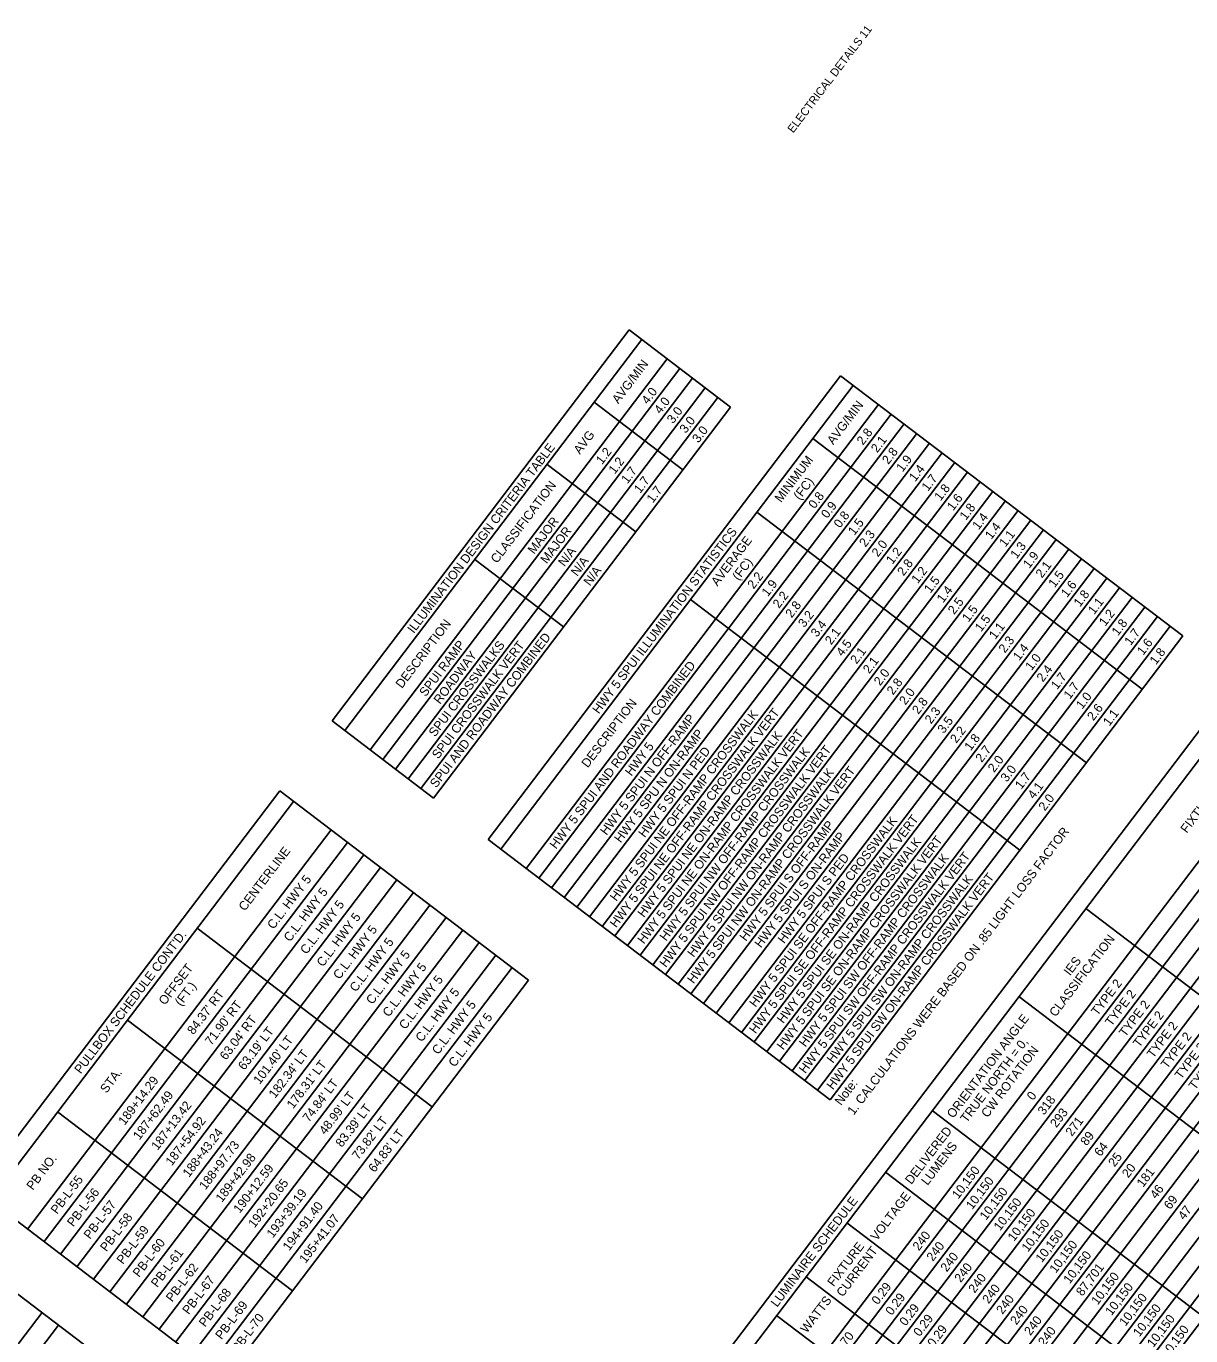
# Model space of a CAD drawing. Extents: x 1289840 to 1300285, y 220865 to 232462.
# Drawn here: x 1298836 to 1299692, y 231499 to 232462 of the extents above; entities that cross this region are included whole.
import ezdxf

# ---------------------------------------------------------------- set-up
doc = ezdxf.new("R2010")
doc.units = 0
for name, color, linetype in [('Default', 7, 'Continuous'), ('R_Border', 7, 'Continuous'), ('R_No Plot', 7, 'Continuous')]:
    doc.layers.add(name, color=color, linetype=linetype)

msp = doc.modelspace()

# ---------------------------------------------------------------- linework, layer by layer
at = {"layer": 'Default'}
for p, q in [((1299060.76, 231951.29), (1299279.23, 232238.61)), ((1299070.07, 231944.21), (1299288.55, 232231.52)), ((1299353.74, 232181.95), (1299279.23, 232238.61)), ((1299088.69, 231930.05), (1299307.17, 232217.36)), ((1299098.01, 231922.96), (1299316.49, 232210.28)), ((1299107.32, 231915.88), (1299325.8, 232203.2)), ((1299175.42, 231864.1), (1299434.62, 232204.96)), ((1299686.08, 232013.75), (1299434.62, 232204.96)), ((1299116.63, 231908.8), (1299335.11, 232196.11)), ((1299184.74, 231857.02), (1299443.93, 232197.88)), ((1299125.95, 231901.72), (1299344.42, 232189.03)), ((1299135.26, 231894.64), (1299353.74, 232181.95)), ((1299203.36, 231842.85), (1299462.56, 232183.72)), ((1299318.68, 232135.85), (1299253.49, 232185.42)), ((1299212.67, 231835.77), (1299471.87, 232176.63)), ((1298957.38, 230970.03), (1299864.22, 232162.59)), ((1299221.99, 231828.69), (1299481.19, 232169.55)), ((1299231.3, 231821.61), (1299490.5, 232162.47)), ((1298967.62, 230962.24), (1299874.46, 232154.8)), ((1299240.61, 231814.52), (1299499.81, 232155.39)), ((1299656.33, 231974.64), (1299414.19, 232158.77)), ((1299249.93, 231807.44), (1299509.13, 232148.31)), ((1299283.98, 232090.21), (1299218.79, 232139.79)), ((1299259.24, 231800.36), (1299518.44, 232141.23)), ((1299268.55, 231793.28), (1299527.75, 232134.14)), ((1299003.48, 230934.98), (1299910.32, 232127.54)), ((1299277.87, 231786.2), (1299537.07, 232127.06)), ((1299013.72, 230927.19), (1299920.56, 232119.75)), ((1299287.18, 231779.12), (1299546.38, 232119.98)), ((1299023.97, 230919.4), (1299930.81, 232111.96)), ((1299296.49, 231772.03), (1299555.69, 232112.9)), ((1299305.81, 231764.95), (1299565.01, 232105.82)), ((1299615.26, 231920.62), (1299373.11, 232104.75)), ((1299034.21, 230911.61), (1299941.05, 232104.17)), ((1299044.46, 230903.82), (1299951.3, 232096.38)), ((1299315.12, 231757.87), (1299574.32, 232098.73)), ((1299054.7, 230896.03), (1299961.54, 232088.59)), ((1299324.43, 231750.79), (1299583.63, 232091.65)), ((1299064.95, 230888.24), (1299971.79, 232080.8)), ((1299333.75, 231743.71), (1299592.95, 232084.57)), ((1299343.06, 231736.62), (1299602.26, 232077.49)), ((1299075.19, 230880.45), (1299982.03, 232073.01)), ((1299230.87, 232020.37), (1299165.67, 232069.94)), ((1299352.37, 231729.54), (1299611.57, 232070.41)), ((1299085.44, 230872.66), (1299992.28, 232065.22)), ((1299095.68, 230864.87), (1300002.52, 232057.43)), ((1299361.69, 231722.46), (1299620.88, 232063.32)), ((1299371, 231715.38), (1299630.2, 232056.24)), ((1299105.93, 230857.08), (1300012.76, 232049.64)), ((1299380.31, 231708.3), (1299639.51, 232049.16)), ((1299116.17, 230849.29), (1300023.01, 232041.85)), ((1299566.39, 231856.36), (1299324.25, 232040.49)), ((1299389.63, 231701.21), (1299648.82, 232042.08)), ((1299126.41, 230841.5), (1300033.25, 232034.06)), ((1299398.94, 231694.13), (1299658.14, 232035)), ((1299408.25, 231687.05), (1299667.45, 232027.91)), ((1299136.66, 230833.71), (1300043.5, 232026.27)), ((1299146.9, 230825.92), (1300053.74, 232018.48)), ((1299417.57, 231679.97), (1299676.76, 232020.83)), ((1299157.15, 230818.13), (1300063.99, 232010.69)), ((1299426.88, 231672.89), (1299686.08, 232013.75)), ((1299167.39, 230810.34), (1300074.23, 232002.9)), ((1299135.26, 231894.64), (1299060.76, 231951.29)), ((1298799.19, 231606.58), (1299022.27, 231899.95)), ((1299205.28, 231760.79), (1299022.27, 231899.95)), ((1298809.43, 231598.79), (1299032.52, 231892.16)), ((1298836.91, 231577.9), (1299059.99, 231871.27)), ((1299426.88, 231672.89), (1299175.42, 231864.1)), ((1298849.02, 231568.7), (1299072.1, 231862.06)), ((1298861.12, 231559.49), (1299084.2, 231852.86)), ((1298873.23, 231550.28), (1299096.31, 231843.65)), ((1298885.34, 231541.08), (1299108.42, 231834.44)), ((1298897.44, 231531.87), (1299120.53, 231825.24)), ((1298909.55, 231522.66), (1299132.63, 231816.03)), ((1298921.66, 231513.46), (1299144.74, 231806.82)), ((1299917.13, 231583.67), (1299614.91, 231813.47)), ((1298933.77, 231504.25), (1299156.85, 231797.62)), ((1299134.46, 231667.66), (1298961.7, 231799.03)), ((1298945.87, 231495.04), (1299168.95, 231788.41)), ((1298957.98, 231485.84), (1299181.06, 231779.2)), ((1298970.09, 231476.63), (1299193.17, 231770)), ((1298982.2, 231467.42), (1299205.28, 231760.79)), ((1299867.91, 231518.94), (1299565.69, 231748.75)), ((1299083.11, 231600.14), (1298910.35, 231731.51)), ((1299031.77, 231532.62), (1298859.01, 231663.99)), ((1299804.17, 231435.12), (1299501.95, 231664.93)), ((1299769.82, 231389.95), (1299467.61, 231619.76)), ((1298982.2, 231467.42), (1298799.19, 231606.58)), ((1299741.49, 231352.7), (1299439.28, 231582.51)), ((1298956.53, 231433.68), (1298773.53, 231572.84)), ((1299711.4, 231313.12), (1299409.18, 231542.92)), ((1298624.49, 231223.17), (1298847.57, 231516.54)), ((1299689.8, 231284.71), (1299387.58, 231514.52)), ((1298636.6, 231213.96), (1298859.68, 231507.33))]:
    msp.add_line(p, q, dxfattribs=at)
at = {"layer": 'R_No Plot'}
for p, q in [((1299060.76, 231951.29), (1299060.76, 231951.29)), ((1299175.42, 231864.1), (1299175.42, 231864.1))]:
    msp.add_line(p, q, dxfattribs=at)

# ---------------------------------------------------------------- texts
at = {"layer": 'Default'}
for s, p in [('AVG/MIN', (1299271.18, 232183.9)), ('4.0', (1299292.85, 232183.41)), ('4.0', (1299302.17, 232176.33)), ('3.0', (1299311.48, 232169.25)), ('AVG/MIN', (1299429.22, 232153.75)), ('3.0', (1299320.79, 232162.17)), ('AVG', (1299242.94, 232146.76)), ('3.0', (1299330.11, 232155.09)), ('2.8', (1299451.07, 232153.49)), ('ILLUMINATION DESIGN CRITERIA TABLE', (1299120.81, 232015.16)), ('2.1', (1299461.52, 232147.9)), ('1.2', (1299259.28, 232139.26)), ('1.2', (1299268.59, 232132.18)), ('MINIMUM', (1299390.77, 232111.36)), ('2.8', (1299469.7, 232139.33)), ('1.9', (1299480.13, 232133.71)), ('1.7', (1299277.91, 232125.1)), ('1.4', (1299489.46, 232126.65)), ('CLASSIFICATION', (1299182.01, 232066.64)), ('1.7', (1299287.22, 232118.02)), ('1.7', (1299296.53, 232110.94)), ('(FC)', (1299404.56, 232113.15)), ('1.7', (1299498.77, 232119.57)), ('1.8', (1299508.08, 232112.49)), ('0.8', (1299415.5, 232106.72)), ('1.6', (1299517.29, 232105.26)), ('0.9', (1299424.8, 232099.62)), ('0.8', (1299434.13, 232092.55)), ('1.8', (1299526.71, 232098.32)), ('MAJOR', (1299209.22, 232073.43)), ('1.5', (1299444.73, 232087.17)), ('1.4', (1299536.02, 232091.24)), ('1.4', (1299545.34, 232084.16)), ('MAJOR', (1299218.54, 232066.35)), ('HWY 5 SPUI ILLUMINATION STATISTICS', (1299256.78, 231955.98)), ('AVERAGE', (1299344.04, 232049.9)), ('2.3', (1299452.91, 232078.6)), ('1.1', (1299555.78, 232078.57)), ('N/A', (1299231.62, 232064.23)), ('2.0', (1299462.05, 232071.29)), ('1.2', (1299472.67, 232065.92)), ('1.3', (1299563.96, 232070)), ('1.9', (1299573.26, 232062.89)), ('N/A', (1299240.94, 232057.15)), ('(FC)', (1299359.59, 232054.01)), ('2.8', (1299480.85, 232057.35)), ('2.1', (1299582.59, 232055.83)), ('N/A', (1299250.25, 232050.07)), ('2.2', (1299370.69, 232047.79)), ('1.2', (1299491.3, 232051.76)), ('1.5', (1299500.61, 232044.68)), ('1.5', (1299591.9, 232048.75)), ('1.9', (1299381.12, 232042.17)), ('1.4', (1299509.93, 232037.59)), ('1.6', (1299601.1, 232041.52)), ('1.8', (1299610.53, 232034.59)), ('2.2', (1299389.32, 232033.62)), ('2.8', (1299398.63, 232026.54)), ('2.5', (1299518.11, 232029.02)), ('1.1', (1299620.97, 232028.99)), ('3.2', (1299407.94, 232019.46)), ('1.5', (1299528.55, 232023.43)), ('1.5', (1299537.87, 232016.35)), ('1.2', (1299629.15, 232020.42)), ('DESCRIPTION', (1299112.12, 231974.73)), ('3.4', (1299417.26, 232012.38)), ('2.1', (1299427.7, 232006.78)), ('1.1', (1299548.31, 232010.76)), ('1.8', (1299638.47, 232013.34)), ('1.7', (1299647.78, 232006.26)), ('SPUI RAMP', (1299129.55, 231968.65)), (' SPUI CROSSWALKS', (1299134.99, 231937.16)), ('SPUI AND ROADWAY COMBINED', (1299137.36, 231901.61)), ('SPUI CROSSWALK VERT', (1299138.8, 231922.84)), ('4.5', (1299435.88, 231998.21)), ('2.3', (1299555.36, 232000.7)), ('1.6', (1299656.98, 231999.03)), ('ROADWAY', (1299140.07, 231963.16)), ('2.1', (1299446.33, 231992.62)), ('1.4', (1299565.81, 231995.1)), ('1.0', (1299574.95, 231987.79)), ('1.8', (1299666.41, 231992.1)), ('HWY 5 SPUI AND ROADWAY COMBINED', (1299225.37, 231856.68)), ('2.1', (1299455.64, 231985.54)), ('2.0', (1299463.65, 231976.74)), ('2.4', (1299583.3, 231979.45)), ('2.8', (1299473.14, 231969.88)), ('1.7', (1299593.74, 231973.86)), ('1.7', (1299603.06, 231966.78)), ('2.0', (1299482.28, 231962.58)), ('1.0', (1299612.2, 231959.47)), ('DESCRIPTION', (1299248.74, 231916.4)), ('HWY 5 SPUI NE OFF-RAMP CROSSWALK VERT', (1299269.61, 231798.88)), ('2.8', (1299491.76, 231955.72)), ('2.3', (1299501.08, 231948.64)), ('2.6', (1299620.44, 231950.98)), ('HWY 5 SPUI N OFF-RAMP', (1299262.49, 231866.84)), ('HWY 5 SPUI NE OFF-RAMP CROSSWALK', (1299269.69, 231818.31)), ('3.5', (1299510.39, 231941.56)), ('1.1', (1299632.13, 231947.02)), ('HWY 5 SPU N ON-RAMP', (1299272.91, 231861.2)), ('HWY 5 SPUI NE ON-RAMP CROSSWALK VERT', (1299289.94, 231786.95)), ('HWY 5 SPUI NE ON-RAMP CROSSWALK', (1299290.01, 231806.38)), ('2.2', (1299519.7, 231934.48)), ('1.8', (1299530.15, 231928.88)), ('HWY 5', (1299280.81, 231910.26)), ('HWY 5 SPUI N PED', (1299290.59, 231865.13)), ('HWY 5 SPUI NW OFF-RAMP CROSSWALK VERT', (1299306.17, 231769.64)), ('HWY 5 SPUI NW OFF-RAMP CROSSWALK', (1299306.25, 231789.07)), ('2.7', (1299538.33, 231920.31)), ('2.0', (1299547.47, 231913)), ('FIXTURE NAME', (1299689.08, 231868.36)), ('HWY 5 SPUI NW ON-RAMP CROSSWALK VERT', (1299326.5, 231757.71)), ('HWY 5 SPUI NW ON-RAMP CROSSWALK', (1299326.57, 231777.14)), ('3.0', (1299556.78, 231905.92)), ('1.7', (1299567.4, 231900.55)), ('4.1', (1299576.71, 231893.47)), ('2.0', (1299584.72, 231884.67)), ('HWY 5 SPUI S OFF-RAMP', (1299364.94, 231788.94)), ('HWY 5 SPUI SE OFF-RAMP CROSSWALK VERT', (1299372.06, 231720.98)), ('HWY 5 SPUI SE OFF-RAMP CROSSWALK', (1299372.13, 231740.41)), ('HWY 5 SPUI S ON-RAMP', (1299375.95, 231784.09)), ('HWY 5 SPUI SE ON-RAMP CROSSWALK VERT', (1299392.38, 231709.05)), ('HWY 5 SPUI SE ON-RAMP CROSSWALK', (1299392.46, 231728.48)), ('1. CALCULATIONS WERE BASED ON .85 LIGHT LOSS FACTOR', (1299444.18, 231661.2)), ('CENTERLINE', (1298996.7, 231811.1)), ('HWY 5 SPUI SW OFF-RAMP CROSSWALK VERT', (1299408.62, 231691.74)), ('HWY 5 SPUI SW OFF-RAMP CROSSWALK', (1299408.69, 231711.17)), ('HWY 5 SPUI S PED', (1299393.03, 231787.22)), ('C.L. HWY 5', (1299017.75, 231797.71)), ('HWY 5 SPUI SW ON-RAMP CROSSWALK VERT', (1299428.94, 231679.81)), ('HWY 5 SPUI SW ON-RAMP CROSSWALK', (1299429.02, 231699.24)), ('C.L. HWY 5', (1299029.86, 231788.5)), ('C.L. HWY 5', (1299041.97, 231779.29)), ('C.L. HWY 5', (1299054.07, 231770.09)), ('C.L. HWY 5', (1299066.18, 231760.88)), ("PULLBOX SCHEDULE CONT'D.", (1298876.01, 231691.53)), ('C.L. HWY 5', (1299078.29, 231751.68)), ('CLASSIFICATION', (1299592.64, 231733.34)), ('C.L. HWY 5', (1299090.4, 231742.47)), ('IES', (1299603.24, 231763.64)), ('OFFSET', (1298937.93, 231741.98)), ('C.L. HWY 5', (1299102.5, 231733.26)), (' (FT.)', (1298948.32, 231739.3)), ('C.L. HWY 5', (1299114.61, 231724.06)), ('TYPE 2', (1299623.43, 231734.18)), ("84.37' RT", (1298958.89, 231720.3)), ('C.L. HWY 5', (1299126.72, 231714.85)), ('TYPE 2', (1299633.68, 231726.39)), ("71.90' RT", (1298971.97, 231712.37)), ('C.L. HWY 5', (1299138.82, 231705.64)), ('TYPE 2', (1299643.92, 231718.6)), ("63.04' RT", (1298982.85, 231701.55)), ('C.L. HWY 5', (1299150.93, 231696.44)), ('ORIENTATION ANGLE', (1299517.34, 231658.85)), ('TYPE 2', (1299654.17, 231710.81)), ('TYPE 2', (1299664.41, 231703.02)), ("63.19' LT", (1298996.34, 231694.17)), ("101.40' LT", (1299007.57, 231683.8)), ('TYPE 2', (1299674.65, 231695.23)), ("182.34' LT", (1299018.86, 231673.52)), ('TRUE NORTH = 0, ', (1299527.26, 231655.55)), ('CW ROTATION', (1299542.55, 231659.3)), ('TYPE 2', (1299684.9, 231687.44)), ("178.31' LT", (1299032.1, 231665.8)), ('TYPE 2', (1299695.14, 231679.65)), ('STA.', (1298894.94, 231677.28)), ('189+14.29', (1298908.27, 231653.73)), ("74.84' LT", (1299043.73, 231655.98)), ('Note:', (1299434.87, 231668.28)), ('187+62.49', (1298919.15, 231642.91)), ('187+13.42', (1298932.5, 231635.34)), ("48.99' LT", (1299055.84, 231646.77)), ('0', (1299576.12, 231671.96)), ('318', (1299584.09, 231661.17)), ("83.39' LT", (1299067.95, 231637.56)), ('293', (1299593.2, 231651.89)), (' 187+54.92', (1298941.48, 231622.01)), ("73.82' LT", (1299080.05, 231628.36)), ('DELIVERED', (1299486.6, 231610.25)), ('271', (1299604.58, 231645.59)), ('188+43.24', (1298955.58, 231615.43)), ('188+97.73', (1298967.69, 231606.23)), ("64.83' LT", (1299092.07, 231619.03)), ('89', (1299615.47, 231638.65)), ('189+42.98', (1298979.79, 231597.02)), ('LUMENS', (1299498.52, 231609.57)), ('64', (1299625.63, 231630.76)), ('25', (1299635.97, 231623.09)), ('PB NO.', (1298840.77, 231606.04)), ('190+12.59', (1298992.86, 231589.08)), ('10,150', (1299521.04, 231599.53)), ('20', (1299646.04, 231615.07)), ('PB-L-55', (1298858.61, 231588.43)), ('192+20.65', (1299003.76, 231578.28)), ('10,150', (1299531.29, 231591.74)), ('181', (1299656.93, 231608.13)), ('PB-L-56', (1298870.61, 231579.07)), ('193+39.19', (1299017.23, 231570.87)), ('VOLTAGE', (1299461.29, 231568.79)), ('10,150', (1299541.53, 231583.95)), ('46', (1299666.59, 231599.58)), ('PB-L-57', (1298882.83, 231570.01)), ('194+91.40', (1299029.18, 231561.46)), ('LUMINAIRE SCHEDULE', (1299387.88, 231520.09)), ('10,150', (1299551.77, 231576.16)), ('69', (1299676.84, 231591.79)), ('47', (1299687.19, 231584.14)), ('PB-L-58', (1298894.93, 231560.81)), ('195+41.07', (1299041.31, 231552.27)), ('10,150', (1299562.02, 231568.37)), ('10,150', (1299572.26, 231560.58)), ('PB-L-59', (1298907.02, 231551.58)), ('240', (1299492.16, 231561.54)), ('10,150', (1299582.51, 231552.79)), ('PB-L-60', (1298918.88, 231542.04)), ('FIXTURE', (1299429.49, 231535.15)), ('CURRENT', (1299436.16, 231527.56)), ('240', (1299502.4, 231553.75)), ('10,150', (1299592.75, 231545)), ('PB-L-61', (1298932.29, 231534.55)), ('240', (1299512.65, 231545.96)), ('10,150', (1299603, 231537.21)), ('PB-L-62', (1298943.27, 231523.86)), ('240', (1299522.89, 231538.17)), ('87,701', (1299612.28, 231528.15)), ('PB-L-67', (1298955.37, 231514.65)), ('0.29', (1299461.97, 231521.84)), ('240', (1299533.14, 231530.38)), ('240', (1299543.38, 231522.59)), ('10,150', (1299623.49, 231521.62)), ('10,150', (1299633.73, 231513.83)), ('PB-L-68', (1298967.48, 231505.44)), ('WATTS', (1299409.72, 231500.97)), ('0.29', (1299472.21, 231514.05)), ('240', (1299553.62, 231514.8)), ('10,150', (1299643.98, 231506.04)), ('PB-L-69', (1298979.57, 231496.22)), ('0.29', (1299482.46, 231506.26)), ('240', (1299563.87, 231507.01)), ('10,150', (1299654.22, 231498.25)), ('PB-L-70', (1298991.62, 231486.93)), ('0.29', (1299492.7, 231498.47)), ('240', (1299574.11, 231499.22)), ('10,150', (1299664.46, 231490.46)), ('70', (1299438.89, 231491.49)), ('0.29', (1299502.95, 231490.68)), ('240', (1299584.36, 231491.43)), ('10,150', (1299674.71, 231482.67))]:
    msp.add_text(s, height=6.6, rotation=52.75013, dxfattribs=at).set_placement(p)
at = {"layer": 'R_Border'}
msp.add_text('ELECTRICAL DETAILS 11', height=6, rotation=52.75194, dxfattribs=at).set_placement((1299399.75, 232382.86))

doc.saveas('drawing.dxf')
